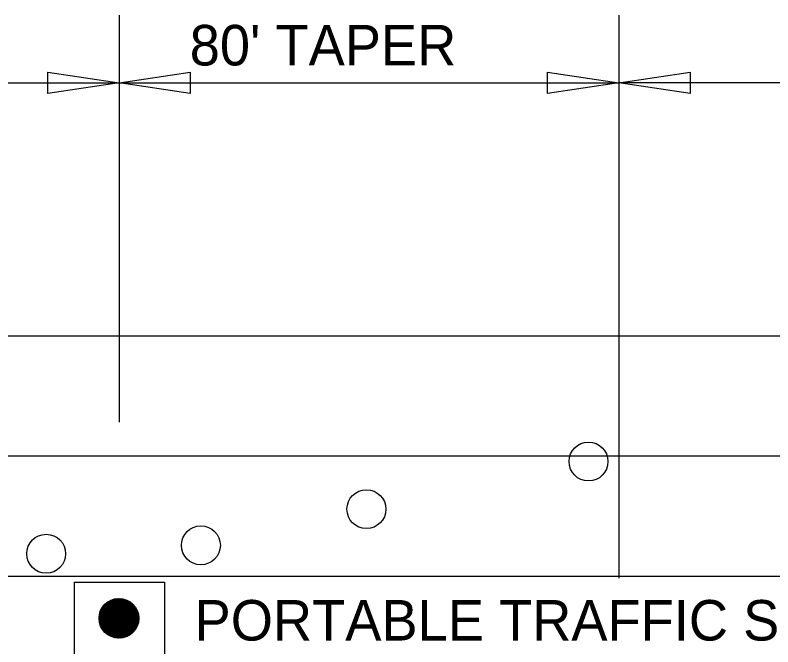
# Model space of a CAD drawing. Extents: x 1926586 to 1930787, y 596452 to 599566.
# Drawn here: x 1928608.4 to 1928720.5, y 597393.4 to 597486.9 of the extents above; entities that cross this region are included whole.
import ezdxf

# ---------------------------------------------------------------- set-up
doc = ezdxf.new("R2010")
doc.units = 0
doc.layers.add('Default', color=7, linetype='Continuous')

msp = doc.modelspace()

# ---------------------------------------------------------------- linework, layer by layer
at = {"layer": 'Default'}
for p, q in [((1928623.8, 597486.95), (1928623.8, 597426.72)), ((1928697.73, 597486.95), (1928697.73, 597426.72)), ((1928613.26, 597475.33), (1928613.26, 597478.49)), ((1928613.26, 597478.49), (1928623.8, 597476.91)), ((1928623.8, 597476.91), (1928634.34, 597478.49)), ((1928634.34, 597478.49), (1928634.34, 597475.33)), ((1928687.19, 597475.33), (1928687.19, 597478.49)), ((1928687.19, 597478.49), (1928697.73, 597476.91)), ((1928697.73, 597476.91), (1928708.28, 597478.49)), ((1928708.28, 597478.49), (1928708.28, 597475.33)), ((1928573.13, 597476.91), (1928623.8, 597476.91)), ((1928623.8, 597476.91), (1928613.26, 597475.33)), ((1928623.8, 597476.91), (1928697.73, 597476.91)), ((1928634.34, 597475.33), (1928623.8, 597476.91)), ((1928697.73, 597476.91), (1928687.19, 597475.33)), ((1928708.28, 597475.33), (1928697.73, 597476.91)), ((1929142.12, 597476.91), (1928697.73, 597476.91)), ((1928697.73, 597455.85), (1928697.73, 597403.63)), ((1927870.1, 597439.49), (1929142.12, 597439.49)), ((1927870.1, 597421.7), (1929142.12, 597421.7)), ((1927870.1, 597403.91), (1929142.12, 597403.91)), ((1928620.84, 597397.71), (1928623.74, 597400.61)), ((1928620.84, 597397.53), (1928623.92, 597400.6)), ((1928620.85, 597397.9), (1928623.55, 597400.6)), ((1928620.85, 597397.36), (1928624.08, 597400.59)), ((1928620.87, 597398.1), (1928623.34, 597400.57)), ((1928620.88, 597397.2), (1928624.24, 597400.57)), ((1928620.9, 597397.05), (1928624.4, 597400.54)), ((1928620.91, 597398.32), (1928623.12, 597400.53)), ((1928620.94, 597396.9), (1928624.54, 597400.51)), ((1928620.98, 597396.76), (1928624.68, 597400.46)), ((1928620.98, 597398.57), (1928622.87, 597400.46)), ((1928621.03, 597396.63), (1928624.82, 597400.42)), ((1928621.08, 597396.5), (1928624.94, 597400.37)), ((1928621.1, 597398.87), (1928622.58, 597400.35)), ((1928621.14, 597396.38), (1928625.07, 597400.31)), ((1928621.2, 597396.26), (1928625.19, 597400.25)), ((1928621.26, 597396.14), (1928625.3, 597400.18)), ((1928621.31, 597399.27), (1928622.18, 597400.13)), ((1928621.33, 597396.03), (1928625.41, 597400.11)), ((1928621.41, 597395.92), (1928625.52, 597400.04)), ((1928621.49, 597395.82), (1928625.62, 597399.96)), ((1928621.57, 597395.72), (1928625.72, 597399.88)), ((1928621.66, 597395.63), (1928625.82, 597399.79)), ((1928621.75, 597395.54), (1928625.91, 597399.7)), ((1928621.84, 597395.45), (1928625.99, 597399.6)), ((1928621.94, 597395.37), (1928626.07, 597399.51)), ((1928622.04, 597395.29), (1928626.15, 597399.4)), ((1928622.15, 597395.22), (1928626.23, 597399.3)), ((1928622.26, 597395.15), (1928626.3, 597399.19)), ((1928622.37, 597395.08), (1928626.36, 597399.07)), ((1928622.49, 597395.02), (1928626.43, 597398.95)), ((1928622.62, 597394.96), (1928626.48, 597398.83)), ((1928622.75, 597394.91), (1928626.53, 597398.7)), ((1928622.88, 597394.86), (1928626.58, 597398.57)), ((1928623.02, 597394.82), (1928626.62, 597398.43)), ((1928623.17, 597394.79), (1928626.66, 597398.28)), ((1928623.32, 597394.76), (1928626.69, 597398.13)), ((1928623.48, 597394.74), (1928626.71, 597397.97)), ((1928623.65, 597394.73), (1928626.72, 597397.8)), ((1928623.82, 597394.72), (1928626.72, 597397.62)), ((1928624.01, 597394.73), (1928626.71, 597397.43)), ((1928624.22, 597394.76), (1928626.69, 597397.23)), ((1928624.44, 597394.8), (1928626.65, 597397)), ((1928624.69, 597394.87), (1928626.58, 597396.75)), ((1928624.99, 597394.98), (1928626.46, 597396.46)), ((1928625.39, 597395.2), (1928626.24, 597396.06))]:
    msp.add_line(p, q, dxfattribs=at)
msp.add_lwpolyline([(1928617.2, 597403.02), (1928630.5, 597403.02), (1928630.5, 597378.48), (1928617.2, 597378.48)], close=True, dxfattribs=at)
for centre, radius in [((1928693.24, 597420.87), 2.88), ((1928660.39, 597413.82), 2.88), ((1928635.9, 597408.46), 2.88), ((1928613.02, 597407.22), 2.88), ((1928623.78, 597397.66), 2.94)]:
    msp.add_circle(centre, radius, dxfattribs=at)

# ---------------------------------------------------------------- texts
for s, p in [("80' TAPER", (1928634.25, 597479.5)), ('PORTABLE TRAFFIC SIGNAL SYSTEM', (1928634.97, 597394.37))]:
    msp.add_text(s, height=6, rotation=360, dxfattribs=at).set_placement(p)

doc.saveas('drawing.dxf')
